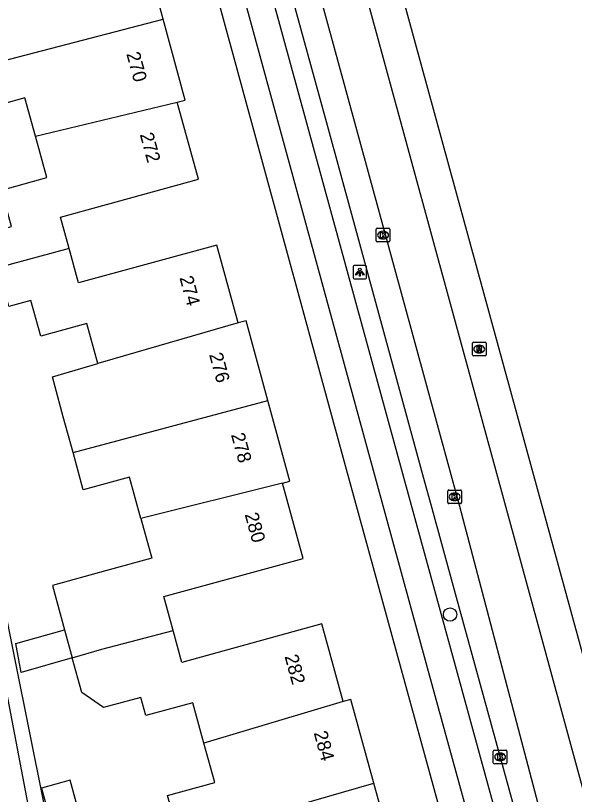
# Model space of a CAD drawing. Extents: x 162250 to 162654, y 380744 to 381605.
# Drawn here: x 162544.6 to 162585.6, y 381043.1 to 381100.2 of the extents above; entities that cross this region are included whole.
import ezdxf

# ---------------------------------------------------------------- set-up
doc = ezdxf.new("R2010")
doc.units = 0
for name, color, linetype in [('IMGEO_Boom', 7, 'Continuous'), ('IMGEO_Fietspad_gesloten', 7, 'Continuous'), ('IMGEO_Kolk', 7, 'Continuous'), ('IMGEO_Lichtpunt', 7, 'Continuous'), ('IMGEO_Pand', 7, 'Continuous'), ('IMGEO_Pand_nummerreeks', 7, 'Continuous'), ('IMGEO_Parkeervlak_open', 7, 'Continuous'), ('IMGEO_Rijbaan_regionaal_gesloten', 7, 'Continuous'), ('IMGEO_Rioolput', 7, 'Continuous'), ('IMGEO_Voetpad_open', 7, 'Continuous')]:
    doc.layers.add(name, color=color, linetype=linetype)

msp = doc.modelspace()

# ---------------------------------------------------------------- linework, layer by layer
at = {"layer": 'IMGEO_Boom'}
msp.add_circle((162576.468, 381056.326), 0.489, dxfattribs=at)
at = {"layer": 'IMGEO_Fietspad_gesloten'}
for points in [[(162536.398, 381200.372), (162539.144, 381190.342), (162540.943, 381183.77), (162548.984, 381154.395), (162551.592, 381144.84), (162551.645, 381144.647), (162554.806, 381133.124), (162560.736, 381111.446), (162562.992, 381103.198), (162573.052, 381066.398), (162577.335, 381050.801), (162584.526, 381024.553), (162587.309, 381014.367), (162588.433, 381010.254), (162590.219, 381003.716), (162603.154, 380956.316), (162606.977, 380942.372), (162608.338, 380937.386), (162611.747, 380924.889), (162613.149, 380919.833), (162613.482, 380918.571)], [(162626.231, 380864.638), (162619.54, 380889.111), (162611.456, 380918.623), (162600.985, 380956.955), (162588.336, 381003.241), (162586.64, 381009.407), (162585.413, 381013.87), (162582.804, 381023.355), (162575.392, 381050.363), (162571.085, 381066.091), (162561.27, 381101.934), (162558.72, 381111.249), (162552.836, 381132.744), (162549.852, 381143.643)]]:
    msp.add_lwpolyline(points, dxfattribs=at)
at = {"layer": 'IMGEO_Kolk'}
for p, q in [((162571.063, 381083.72), (162571.063, 381084.572)), ((162571.138, 381084.646), (162571.99, 381084.646)), ((162571.551, 381084.426), (162571.576, 381084.426)), ((162572.064, 381084.572), (162572.064, 381083.72)), ((162571.574, 381083.866), (162571.549, 381083.866)), ((162571.99, 381083.646), (162571.138, 381083.646)), ((162576.306, 381064.532), (162576.306, 381065.384)), ((162576.381, 381065.458), (162577.233, 381065.458)), ((162576.794, 381065.238), (162576.819, 381065.238)), ((162577.307, 381065.384), (162577.307, 381064.532)), ((162577.233, 381064.458), (162576.381, 381064.458)), ((162576.817, 381064.678), (162576.792, 381064.678)), ((162579.643, 381045.459), (162579.643, 381046.311)), ((162579.718, 381046.385), (162580.57, 381046.385)), ((162580.131, 381046.165), (162580.156, 381046.165)), ((162580.644, 381046.311), (162580.644, 381045.459)), ((162580.154, 381045.605), (162580.129, 381045.605)), ((162580.57, 381045.385), (162579.718, 381045.385))]:
    msp.add_line(p, q, dxfattribs=at)
for points in [[(162571.063, 381083.72), (162571.063, 381084.572)], [(162571.138, 381084.646), (162571.99, 381084.646)], [(162572.064, 381084.572), (162572.064, 381083.72)], [(162571.384, 381084.346), (162571.507, 381084.346), (162571.507, 381084.195), (162571.637, 381084.346), (162571.801, 381084.346), (162571.655, 381084.195), (162571.808, 381083.946), (162571.656, 381083.946), (162571.571, 381084.11), (162571.507, 381084.043), (162571.507, 381083.946), (162571.384, 381083.946), (162571.384, 381084.346)], [(162571.99, 381083.646), (162571.138, 381083.646)], [(162576.306, 381064.532), (162576.306, 381065.384)], [(162576.381, 381065.458), (162577.233, 381065.458)], [(162576.627, 381065.158), (162576.75, 381065.158), (162576.75, 381065.007), (162576.88, 381065.158), (162577.044, 381065.158), (162576.898, 381065.007), (162577.051, 381064.758), (162576.899, 381064.758), (162576.814, 381064.922), (162576.75, 381064.855), (162576.75, 381064.758), (162576.627, 381064.758), (162576.627, 381065.158)], [(162577.307, 381065.384), (162577.307, 381064.532)], [(162577.233, 381064.458), (162576.381, 381064.458)], [(162579.643, 381045.459), (162579.643, 381046.311)], [(162579.718, 381046.385), (162580.57, 381046.385)], [(162580.644, 381046.311), (162580.644, 381045.459)], [(162579.964, 381046.085), (162580.087, 381046.085), (162580.087, 381045.934), (162580.217, 381046.085), (162580.381, 381046.085), (162580.235, 381045.934), (162580.388, 381045.685), (162580.236, 381045.685), (162580.151, 381045.849), (162580.087, 381045.782), (162580.087, 381045.685), (162579.964, 381045.685), (162579.964, 381046.085)], [(162580.57, 381045.385), (162579.718, 381045.385)]]:
    msp.add_lwpolyline(points, dxfattribs=at)
for centre, start, end in [((162571.14, 381084.57), 91.552, 178.448), ((162571.14, 381084.57), 91.552, 178.448), ((162571.988, 381084.57), 1.552, 88.448), ((162571.988, 381084.57), 1.552, 88.448), ((162571.14, 381083.722), 181.552, 268.448), ((162571.14, 381083.722), 181.552, 268.448), ((162571.988, 381083.722), 271.552, 358.448), ((162571.988, 381083.722), 271.552, 358.448), ((162576.383, 381065.382), 91.552, 178.448), ((162576.383, 381065.382), 91.552, 178.448), ((162577.231, 381065.382), 1.552, 88.448), ((162577.231, 381065.382), 1.552, 88.448), ((162576.383, 381064.534), 181.552, 268.448), ((162576.383, 381064.534), 181.552, 268.448), ((162577.231, 381064.534), 271.552, 358.448), ((162577.231, 381064.534), 271.552, 358.448), ((162579.72, 381046.309), 91.552, 178.448), ((162579.72, 381046.309), 91.552, 178.448), ((162580.568, 381046.309), 1.552, 88.448), ((162580.568, 381046.309), 1.552, 88.448), ((162579.72, 381045.461), 181.552, 268.448), ((162579.72, 381045.461), 181.552, 268.448), ((162580.568, 381045.461), 271.552, 358.448), ((162580.568, 381045.461), 271.552, 358.448)]:
    msp.add_arc(centre, 0.0765, start, end, dxfattribs=at)
for centre, major_axis, ratio, start_param, end_param in [((162571.55, 381084.146), (-0.387, 0.002), 0.722429, 4.712389, 7.853982), ((162571.575, 381084.146), (-0.39, 0.002), 0.717154, 1.570796, 4.712389), ((162576.793, 381064.958), (-0.387, 0.002), 0.722429, 4.712389, 7.853982), ((162576.818, 381064.958), (-0.39, 0.002), 0.717154, 1.570796, 4.712389), ((162580.13, 381045.885), (-0.387, 0.002), 0.722429, 4.712389, 7.853982), ((162580.155, 381045.885), (-0.39, 0.002), 0.717154, 1.570796, 4.712389)]:
    msp.add_ellipse(centre, major_axis=major_axis, ratio=ratio, start_param=start_param, end_param=end_param, dxfattribs=at)
at = {"layer": 'IMGEO_Lichtpunt'}
for p, q in [((162569.359, 381081.832), (162569.359, 381081.025)), ((162569.359, 381081.832), (162569.359, 381081.025)), ((162570.261, 381081.927), (162569.453, 381081.927)), ((162570.261, 381081.927), (162569.453, 381081.927)), ((162570.355, 381081.025), (162570.355, 381081.832)), ((162570.355, 381081.025), (162570.355, 381081.832)), ((162569.453, 381080.931), (162570.261, 381080.931)), ((162569.453, 381080.931), (162570.261, 381080.931))]:
    msp.add_line(p, q, dxfattribs=at)
for points in [[(162569.733, 381081.496), (162569.772, 381081.468), (162569.584, 381081.206), (162569.546, 381081.233), (162569.733, 381081.496)], [(162569.835, 381081.448), (162569.882, 381081.448), (162569.882, 381081.126), (162569.835, 381081.126), (162569.835, 381081.448)], [(162569.945, 381081.468), (162569.983, 381081.495), (162570.17, 381081.233), (162570.131, 381081.205), (162569.945, 381081.468)]]:
    msp.add_lwpolyline(points, dxfattribs=at)
msp.add_circle((162569.858, 381081.63), 0.0994, dxfattribs=at)
for centre, start, end in [((162569.453, 381081.832), 90, 180), ((162569.453, 381081.832), 90, 180), ((162570.261, 381081.832), 0, 90), ((162570.261, 381081.832), 0, 90), ((162569.453, 381081.025), 180, 270), ((162569.453, 381081.025), 180, 270), ((162570.261, 381081.025), 270, 0), ((162570.261, 381081.025), 270, 360)]:
    msp.add_arc(centre, 0.0946, start, end, dxfattribs=at)
at = {"layer": 'IMGEO_Pand'}
for points in [[(162555.439, 381099.973), (162553.915, 381105.543)], [(162541.231, 381096.275), (162555.439, 381099.973)], [(162556.474, 381093.882), (162557.061, 381094.043), (162555.439, 381099.973)], [(162546.076, 381091.407), (162545.31, 381094.206), (162542.041, 381093.312), (162541.825, 381094.103)], [(162546.076, 381091.407), (162556.474, 381093.882)], [(162548.545, 381083.169), (162547.915, 381085.473), (162558.019, 381088.236), (162556.474, 381093.882)], [(162543.338, 381081.751), (162539.472, 381080.698), (162538.769, 381083.264), (162542.634, 381084.323), (162544.31, 381084.782), (162543.58, 381087.45), (162546.909, 381088.36), (162546.076, 381091.407)], [(162560.935, 381077.702), (162559.372, 381083.419), (162549.235, 381080.647), (162548.545, 381083.169)], [(162548.545, 381083.169), (162544.122, 381081.964), (162543.338, 381081.751)], [(162550.658, 381074.726), (162549.856, 381077.659), (162546.462, 381076.731), (162545.743, 381079.357), (162544.114, 381078.912), (162543.338, 381081.751)], [(162560.935, 381077.702), (162551.76, 381075.045), (162550.658, 381074.726)], [(162563.119, 381072.025), (162561.523, 381077.861), (162560.935, 381077.702)], [(162548.835, 381068.201), (162548.121, 381070.812), (162547.315, 381073.758), (162550.658, 381074.726)], [(162548.835, 381068.201), (162563.119, 381072.025)], [(162564.181, 381065.963), (162564.736, 381066.115), (162563.119, 381072.025)], [(162553.801, 381063.367), (162552.969, 381066.408), (162549.579, 381065.481), (162548.835, 381068.201)], [(162564.181, 381065.963), (162553.801, 381063.367)], [(162556.178, 381055.147), (162555.492, 381057.653), (162565.692, 381060.447), (162564.181, 381065.963)], [(162553.801, 381063.367), (162554.598, 381060.451), (162551.217, 381059.526), (162547.319, 381058.46), (162548.208, 381055.212)], [(162568.637, 381049.954), (162567.082, 381055.635), (162556.815, 381052.823), (162556.178, 381055.147)], [(162548.77, 381053.157), (162545.02, 381052.083), (162544.646, 381054.192), (162548.208, 381055.212)], [(162548.208, 381055.212), (162548.77, 381053.157)], [(162548.77, 381053.157), (162550.938, 381053.778), (162556.178, 381055.147)], [(162558.423, 381046.902), (162557.612, 381049.866), (162554.168, 381048.924), (162553.804, 381050.253), (162551.065, 381049.503), (162549.468, 381050.604), (162548.77, 381053.157)], [(162568.637, 381049.954), (162558.423, 381046.902)], [(162570.878, 381043.971), (162569.197, 381050.108), (162568.637, 381049.954)], [(162556.556, 381040.18), (162555.768, 381043.062), (162559.216, 381044.005), (162558.423, 381046.902)], [(162546.517, 381043.608), (162547.768, 381039.032), (162549.88, 381039.609), (162548.629, 381044.186), (162546.517, 381043.608)], [(162556.556, 381040.18), (162556.744, 381040.233), (162556.829, 381039.919), (162570.878, 381043.971)], [(162571.849, 381038.288), (162572.393, 381038.437), (162570.878, 381043.971)]]:
    msp.add_lwpolyline(points, dxfattribs=at)
at = {"layer": 'IMGEO_Parkeervlak_open'}
msp.add_lwpolyline([(162582.831, 381036.134), (162576.877, 381057.835), (162575.087, 381064.36), (162574.627, 381066.044), (162569.261, 381085.65), (162567.483, 381092.185), (162564.577, 381102.79)], dxfattribs=at)
at = {"layer": 'IMGEO_Rijbaan_regionaal_gesloten'}
for points in [[(162571.442, 381107.069), (162572.292, 381104.139), (162600.62, 381000.709)], [(162565.639, 381106.468), (162577.173, 381064.266), (162584.449, 381036.623)], [(162598.128, 380999.927), (162593.627, 381016.375), (162570.083, 381102.662), (162569.2, 381106.245)]]:
    msp.add_lwpolyline(points, dxfattribs=at)
at = {"layer": 'IMGEO_Rioolput'}
for p, q in [((162578.107, 381075.363), (162578.107, 381076.215)), ((162578.182, 381076.289), (162579.034, 381076.289)), ((162578.595, 381076.069), (162578.62, 381076.069)), ((162579.108, 381076.215), (162579.108, 381075.363)), ((162579.034, 381075.289), (162578.182, 381075.289)), ((162578.618, 381075.509), (162578.593, 381075.509))]:
    msp.add_line(p, q, dxfattribs=at)
for points in [[(162578.107, 381075.363), (162578.107, 381076.215)], [(162578.182, 381076.289), (162579.034, 381076.289)], [(162578.696, 381075.987), (162578.444, 381075.989), (162578.444, 381075.589)], [(162578.622, 381075.908), (162578.568, 381075.908), (162578.568, 381075.827)], [(162578.568, 381075.827), (162578.62, 381075.827)], [(162579.108, 381076.215), (162579.108, 381075.363)], [(162579.034, 381075.289), (162578.182, 381075.289)], [(162578.444, 381075.589), (162578.568, 381075.589), (162578.568, 381075.751), (162578.579, 381075.751)], [(162578.626, 381075.722), (162578.697, 381075.589), (162578.837, 381075.589), (162578.772, 381075.715)]]:
    msp.add_lwpolyline(points, dxfattribs=at)
for centre, radius, start, end in [((162578.184, 381076.213), 0.0765, 91.552, 178.448), ((162578.184, 381076.213), 0.0765, 91.552, 178.448), ((162578.604, 381076.016), 0.19, 274.7715, 282.9687), ((162578.628, 381075.812), 0.0964, 77.0061, 93.1865), ((162578.642, 381075.869), 0.0378, 276.6634, 79.6772), ((162578.695, 381075.877), 0.109, 350.3612, 89.416), ((162578.693, 381075.877), 0.112, 277.5842, 350.9817), ((162579.032, 381076.213), 0.0765, 1.552, 88.448), ((162579.032, 381076.213), 0.0765, 1.552, 88.448), ((162578.184, 381075.365), 0.0765, 181.552, 268.448), ((162578.184, 381075.365), 0.0765, 181.552, 268.448), ((162578.578, 381075.698), 0.0533, 26.0293, 88.6989), ((162578.677, 381075.662), 0.108, 29.5134, 73.7905), ((162579.032, 381075.365), 0.0765, 271.552, 358.448), ((162579.032, 381075.365), 0.0765, 271.552, 358.448)]:
    msp.add_arc(centre, radius, start, end, dxfattribs=at)
for centre, major_axis, ratio, start_param, end_param in [((162578.594, 381075.789), (-0.387, 0.002), 0.722429, 4.712389, 7.853982), ((162578.619, 381075.789), (-0.39, 0.002), 0.717154, 1.570796, 4.712389)]:
    msp.add_ellipse(centre, major_axis=major_axis, ratio=ratio, start_param=start_param, end_param=end_param, dxfattribs=at)
at = {"layer": 'IMGEO_Voetpad_open'}
for points in [[(162548.044, 381143.201), (162550.23, 381135.191), (162568.771, 381067.243), (162583.561, 381013.383), (162590.707, 380987.36)], [(162548.818, 381031.958), (162533.885, 381106.188)], [(162543.553, 381052.67), (162545.431, 381042.907), (162551.707, 381011.128)]]:
    msp.add_lwpolyline(points, dxfattribs=at)

# ---------------------------------------------------------------- texts
at = {"layer": 'IMGEO_Pand_nummerreeks'}
for s, rotation, p in [('270', 285.2978, (162552.732, 381097.437)), ('272', 285.3035, (162553.718, 381091.526)), ('274', 285.2978, (162556.627, 381081.024)), ('276', 285.2978, (162558.799, 381075.388)), ('278', 285.2984, (162560.406, 381069.512)), ('280', 285.3207, (162561.41, 381063.665)), ('282', 285.308, (162564.331, 381053.261)), ('284', 285.3145, (162566.468, 381047.653))]:
    msp.add_text(s, height=1, rotation=rotation, dxfattribs=at).set_placement(p)

doc.saveas('drawing.dxf')
